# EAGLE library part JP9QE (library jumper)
JUMPER
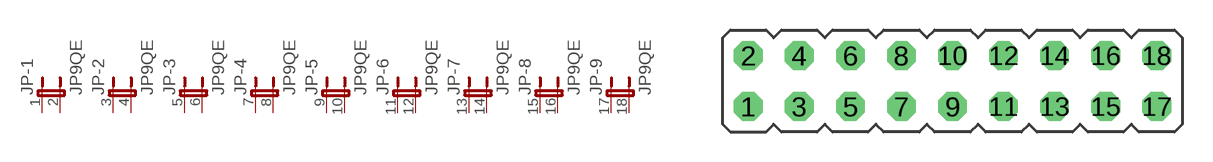
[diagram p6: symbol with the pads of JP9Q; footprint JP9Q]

Designator prefix JP; gates -1=JP2E -2=JP2E -3=JP2E -4=JP2E -5=JP2E -6=JP2E -7=JP2E -8=JP2E -9=JP2E

## JP9QE  [JP9Q]
1  -1:1  pas
2  -1:2  pas
3  -2:1  pas
4  -2:2  pas
5  -3:1  pas
6  -3:2  pas
7  -4:1  pas
8  -4:2  pas
9  -5:1  pas
10  -5:2  pas
11  -6:1  pas
12  -6:2  pas
13  -7:1  pas
14  -7:2  pas
15  -8:1  pas
16  -8:2  pas
17  -9:1  pas
18  -9:2  pas

## Footprint JP9Q (pad centres in mm)
JUMPER
drill 0.914 octagon: 1 -10.16,-1.27; 2 -10.16,1.27; 3 -7.62,-1.27; 4 -7.62,1.27; 5 -5.08,-1.27; 6 -5.08,1.27; 7 -2.54,-1.27; 8 -2.54,1.27; 9 0,-1.27; 10 0,1.27; 11 2.54,-1.27; 12 2.54,1.27; 13 5.08,-1.27; 14 5.08,1.27; 15 7.62,-1.27; 16 7.62,1.27; 17 10.16,-1.27; 18 10.16,1.27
